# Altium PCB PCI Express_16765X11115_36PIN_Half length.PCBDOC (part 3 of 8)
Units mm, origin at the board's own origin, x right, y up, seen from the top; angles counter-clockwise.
Board outline 178 x 110.97 mm, 10 copper layers (Top Layer, Int1 (GND), Int2 (Sign), Int3 (Sign), Int4 (PWR), Int5 (GND), Int6 (Sign), Int7 (Sign), Int8 (GND), Bottom Layer), stack 1.429 mm thick; 528 components, 525 nets, 2272 pads, 1491 vias.
Unrouted connection lines stored in the file: 373.
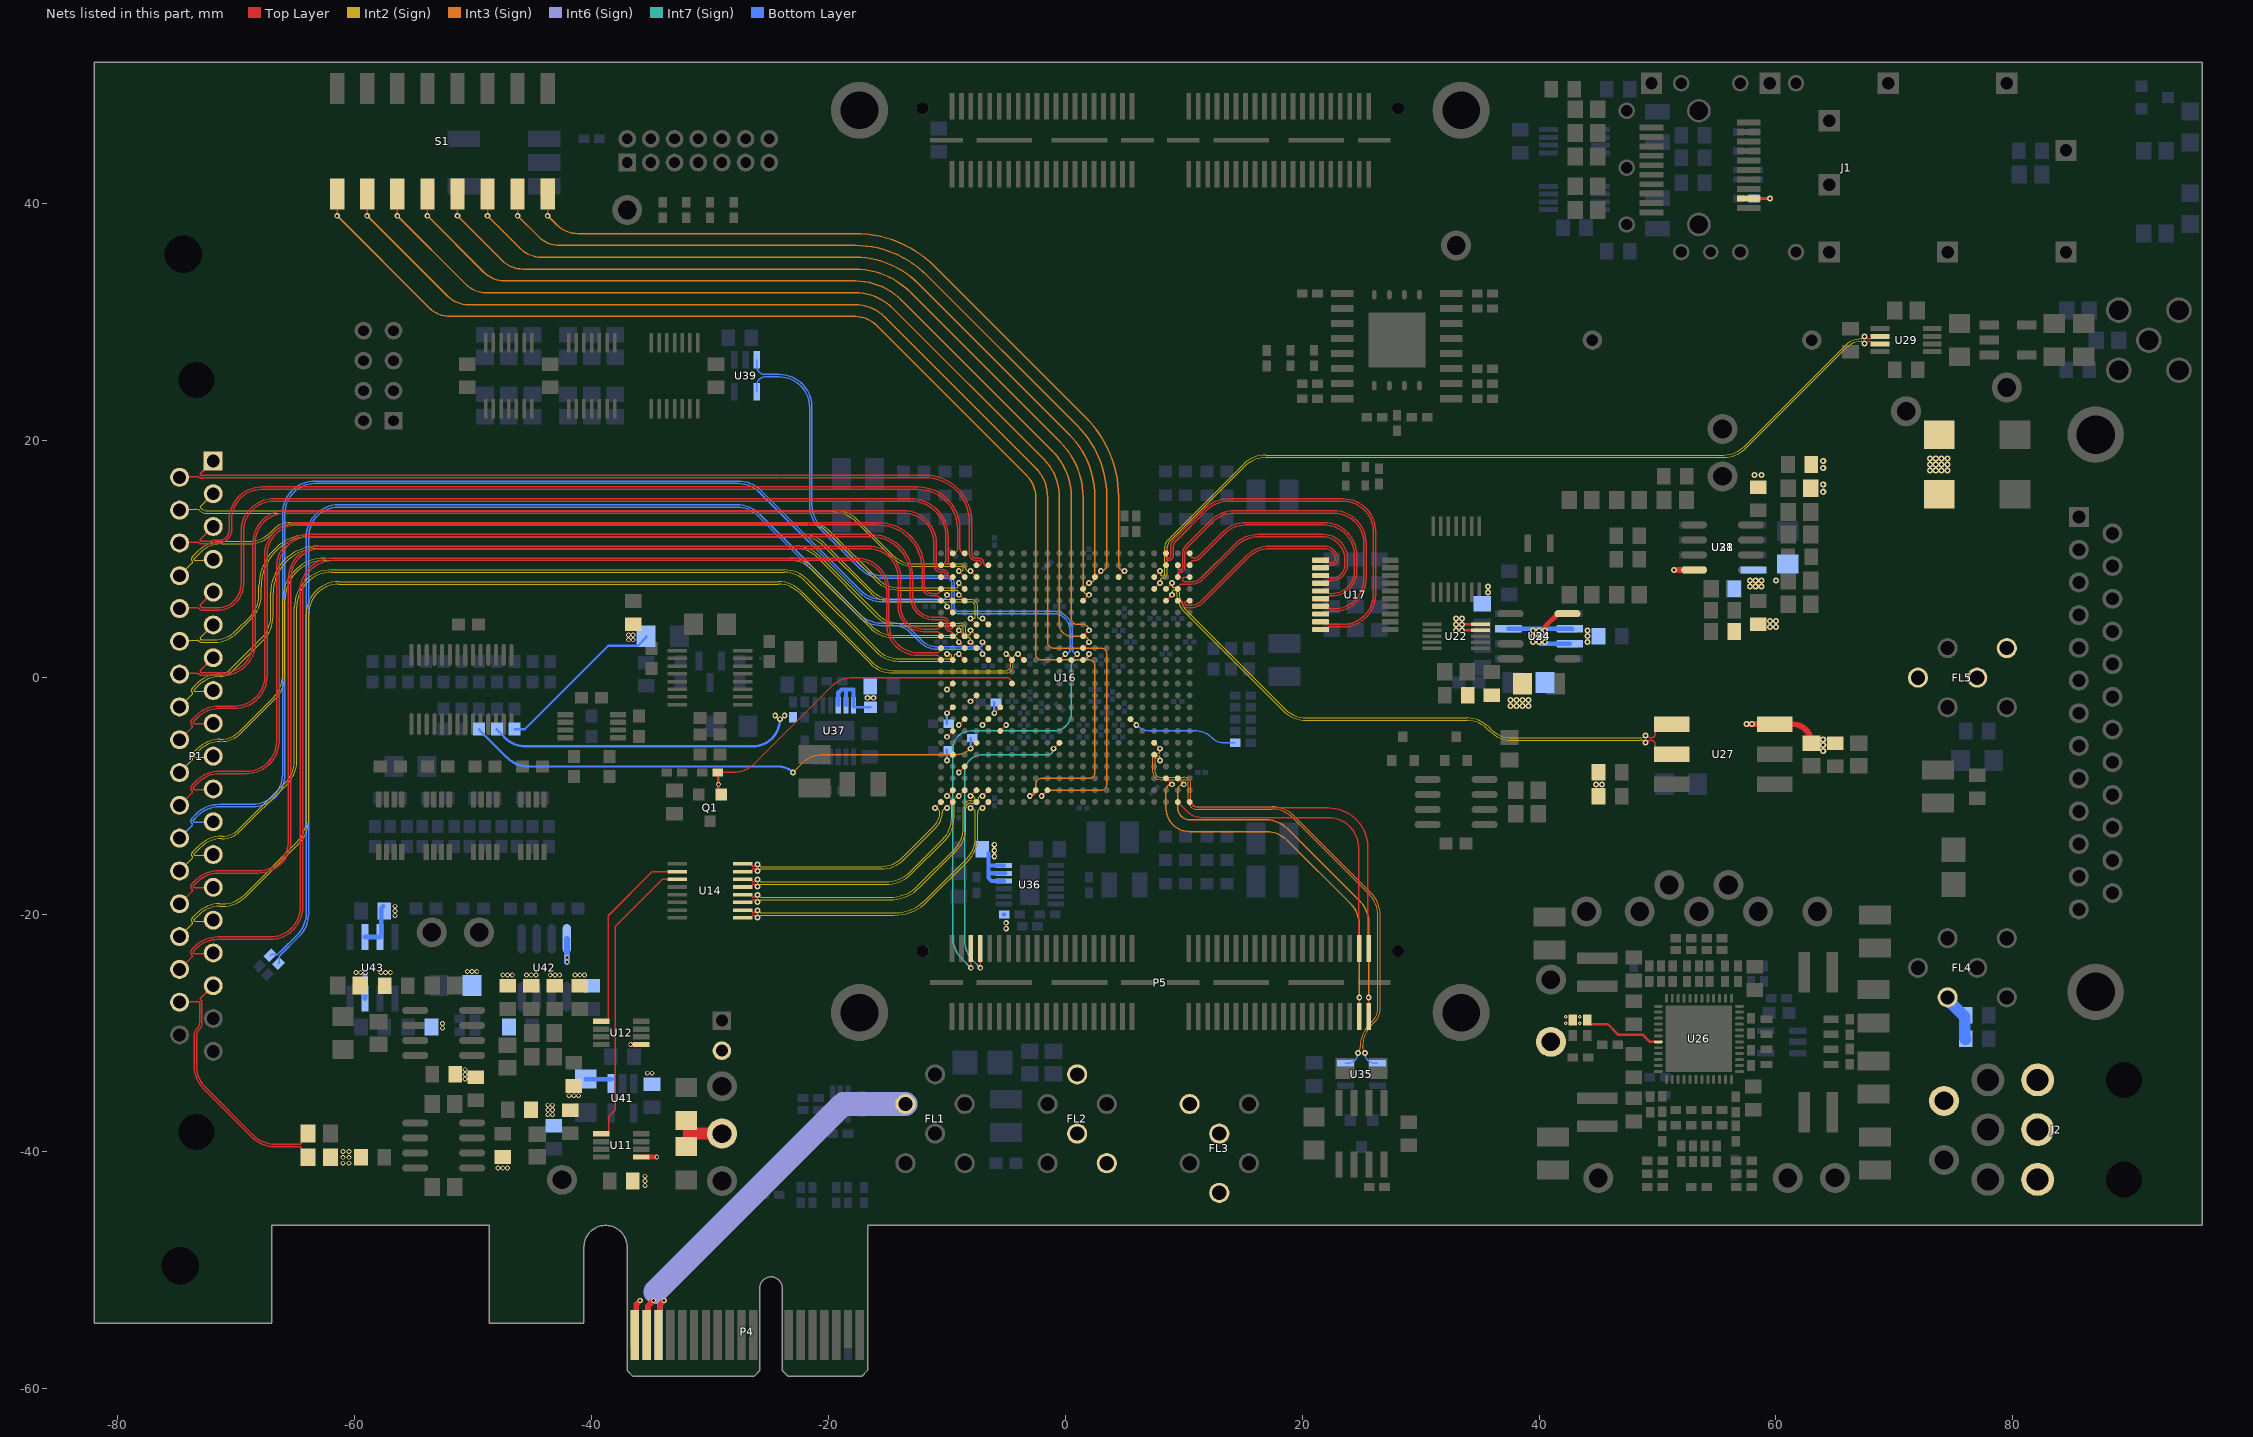
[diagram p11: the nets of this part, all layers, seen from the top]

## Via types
v1: diameter 0.483, hole 0.254, Top Layer to Bottom Layer, tented both sides, 740 vias
v2: diameter 0.508, hole 0.254, Top Layer to Bottom Layer, tented both sides, 302 vias
v3: diameter 0.406, hole 0.254, Top Layer to Bottom Layer, tented both sides, 267 vias
v4: diameter 0.305, hole 0.152, Top Layer to Bottom Layer, tented both sides, 95 vias
v5: diameter 0.5, hole 0.254, Top Layer to Bottom Layer, tented both sides, 50 vias
v6: diameter 0.45, hole 0.254, Top Layer to Bottom Layer, tented both sides, 23 vias
v7: diameter 0.6, hole 0.254, Top Layer to Bottom Layer, tented both sides, 14 vias

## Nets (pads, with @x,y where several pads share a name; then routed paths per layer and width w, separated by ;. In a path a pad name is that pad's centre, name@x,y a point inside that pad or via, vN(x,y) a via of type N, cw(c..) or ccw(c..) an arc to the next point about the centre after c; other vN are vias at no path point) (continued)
AGND: C30.1 C33.1 C34.2 C38.1 C39.1 C54.1 C62.1 C63.1 C65.1 C66.2 C71.2 C72.2 C81.2 C82.1 C88.1 C90.2 FL5.4 FL5.5 FL5.6 R91.2 R92.2 R128.2 U22.4 U22.5 U24.4 U27.3 U28.4 U31.4 U34.3 U34.6 U34.7 | length 22.5
  Top Layer w0.203: U22.4@35.05,4 v2(33.5,4) v2(33.5,4.5) U22.5@35.05,4.5 ; C66.2@64.95,-5.55 ccw(c64.95,-5.5) C66.2@65,-5.5
  Top Layer w0.406: v2(40.5,4) 40.52,4.02 40.52,4.325 41.6,5.405 U24.4@42.4,5.405 U24.4@42.403,5.403
  Top Layer w0.5: v2(51.4,9.1) 53.095,9.1 U28.4@53.1,9.095 ; v2(57.537,-3.92) v2(58,-3.92) U27.3@59.9,-3.92 61.37,-3.92 cw(c61.37,-5.55) R92.2@63,-5.55
  Bottom Layer w0.406: U34.3@37.4,4.135 U34.6@42.6,4.135 42.765,4.135 U34.6@42.8,4.1 ; v2(40,3) 40.135,2.865 U34.7@42.6,2.865
  other v2: 44.8,-9 45.3,-9 64,-6.2 64,-5.7 64,-5.2 37.6,-2.4 38.1,-2.4 38.6,-2.4 39.1,-2.4 37.6,-1.9 38.1,-1.9 38.6,-1.9 39.1,-1.9 39.5,3 40.5,3 44.1,3 39.5,3.5 40,3.5 40.5,3.5 44.1,3.5 33,4 39.5,4 40,4 44.1,4 59.5,4.3 60,4.3 33,4.502 59.5,4.8 60,4.8 33,5 33.5,5 35.7,7.2 35.7,7.7 57.8,7.7 58.3,7.7 58.8,7.7 57.8,8.2 58.3,8.2 58.8,8.2 60,8.2 64,15.7 64,16.3 58.2,17.1 58.8,17.1 73,17.5 73.5,17.5 74,17.5 74.5,17.5 64,17.7 73,18 73.5,18 74,18 74.5,18 64,18.3 73,18.5 73.5,18.5 74,18.5 74.5,18.5
AVCC: C161.2 C165.2 C166.2 R140.2 R181.1 U16.D6 U16.D10 U16.E8 U16.F7 U16.F9 U36.10 U36.11 U36.12 | length 55.2
  Top Layer w0.127: v1(-8,-6) U16.D6@-7.5,-5.5 ; v1(-8,-2) U16.D10@-7.5,-1.5 ; v1(-7,-4) U16.E8@-6.5,-3.5 ; v1(-6,-3) U16.F9@-5.5,-2.5 ; U16.F7@-5.5,-4.5 v1(-5,-4)
  Int3 (Sign) w0.127: v1(-23,-8) -22.244,-7.244 cw(c-20.448,-9.04) -20.448,-6.5 -9.207,-6.5 ccw(c-9.207,-4.793) v1(-8,-6)
  Bottom Layer w0.127: C161.2@-6.1,-2 C161.2@-6,-2.1
  Bottom Layer w0.203: R181.1@-49.5,-4.35 -49.5,-4.4 -47.144,-6.756 ccw(c-45.348,-4.96) -45.348,-7.5 -24.207,-7.5 cw(c-24.207,-9.207) v1(-23,-8) ; v1(-8,-6) C166.2@-8,-5.1 ; v1(-6,-3) C161.2@-6,-2.1
  Bottom Layer w0.35: C165.2@-6.5,-14.8 -6.5,-15.9 ; -6.351,-16.519 U36.11@-5.061,-16.519 ; R140.2@-5.225,-20 R140.2@-5.15,-20 ; U36.12@-5.209,-15.9 U36.12@-5.184,-15.875 -6.475,-15.875 -6.5,-15.9 ; U36.10@-5.184,-17.175 -6.225,-17.175 -6.5,-16.9 -6.5,-15.9
  other v1: -5,-21.2 -5,-20.7 -6,-15.1 -6,-14.6 -6,-14.1
AVCC1V8: C18.1 C37.2 FR5.1 R58.2 R170.1 TP9.1 U26.7 | length 21.2
  Top Layer w0.203: C37.2@44.062,-28.912 44.062,-29.012 44.311,-29.261 45.821,-29.261 46.719,-30.159 48.793,-30.159 49.383,-30.75 U26.7@50.075,-30.75
  Bottom Layer w0.203: R170.1@-46.5,-4.35 -45.65,-4.35 -38.6,2.7 -36.217,2.7 -36.216,2.702 -36.098,2.702 -35.4,3.4 FR5.1@-35.4,3.5
  other v3: -36.9,3.2 -36.5,3.2 -36.9,3.6 -36.5,3.6
  other v4: 42.25,-29.187 43.437,-29.187 42.25,-28.625 43.437,-28.625
AVTT: C173.2 C174.2 C181.2 R144.2 R152.2 R175.1 U16.B5 U16.B7 U16.B9 U16.B11 U16.C4 U16.C8 U37.10 U37.11 U37.12 | length 38.3
  Top Layer w0.127: v1(-10,-7) U16.B5@-9.5,-6.5 ; v1(-10,-5) U16.B7@-9.5,-4.5 ; v1(-10,-3) U16.B9@-9.5,-2.5 ; v1(-10,-1) U16.B11@-9.5,-0.5 ; v1(-9,-8) U16.C4@-8.5,-7.5 ; v1(-9,-4) U16.C8@-8.5,-3.5
  Bottom Layer w0.203: R175.1@-48,-4.35 -48,-4.4 -47.342,-5.058 ccw(c-45.546,-3.262) -45.546,-5.802 -28.7,-5.802 ; -28.7,-5.8 -26.4,-5.8 ccw(c-26.4,-3.5) v1(-24.1,-3.5) ; U37.12@-17.9,-2.5 R144.2@-16.45,-2.5 ; v1(-10,-7) C173.2@-10,-6.1 ; C174.2@-10,-3.9 v1(-10,-3)
  Bottom Layer w0.35: U37.10@-19.175,-2.316 -19.175,-1.275 -18.9,-1 -17.875,-1 U37.12@-17.875,-2.316 ; U37.11@-18.525,-2.316 -18.525,-1.025
  other v1: -24.5,-3.2 -23.7,-3.2 -16.7,-1.7 -16.2,-1.7
BACKPLANE.CLK0_N: P1.21 U16.C20 | length 69.3
  Top Layer w0.127: v1(-9,9) U16.C20@-8.5,8.5
  Int2 (Sign) w0.076: P1.21@-74.795,14.15 cw(c-74.615,13.97) -74.615,14.225 -73.434,14.225 cw(c-73.434,13.665) -73.038,14.061 ccw(c-72.642,14.457) -72.642,13.897 -19.449,13.897 cw(c-19.449,11.357) -17.653,13.153 -14.703,10.203 ccw(c-12.764,12.142) -12.764,9.4 -8.802,9.4 cw(c-8.802,9.2) -8.602,9.2 cw(c-8.802,9.2) -8.802,9 v1(-9,9)
BACKPLANE.CLK0_P: P1.2 U16.D20 | length 69.4
  Top Layer w0.127: v1(-8,9) U16.D20@-7.5,8.5
  Int2 (Sign) w0.076: P1.2@-71.955,15.535 -73.036,14.454 ccw(c-72.982,14.4) -73.059,14.4 ccw(c-72.982,14.4) -73.036,14.346 ccw(c-72.442,14.94) -72.442,14.1 -19.448,14.1 cw(c-19.448,11.359) -17.51,13.297 -14.56,10.347 ccw(c-12.764,12.143) -12.764,9.603 -8.802,9.603 cw(c-8.802,9.2) -8.398,9.2 ccw(c-8.198,9.2) -8.198,9 v1(-8,9)
BACKPLANE.CLK1_N: P1.30 U16.B16 | length 90.3
  Top Layer w0.127: P1.30@-74.795,-10.78 -73.75,-9.735 ccw(c-73.84,-9.645) -73.713,-9.645 ccw(c-73.84,-9.645) -73.75,-9.555 ; -73.751,-9.554 cw(c-73.519,-9.323) -73.846,-9.323 -73.846,-9.32 cw(c-73.52,-9.32) -73.751,-9.089 -73.361,-8.7 cw(c-71.423,-10.637) -71.423,-7.897 -69.143,-7.897 ccw(c-69.143,-5.357) -66.603,-5.357 -66.603,9.36 cw(c-63.86,9.36) -63.86,12.103 -16.453,12.103 cw(c-16.453,8.547) -12.897,8.547 -12.897,6.793 ccw(c-11.098,6.9) -11.098,5.098 -10.336,5.098 cw(c-10.336,4.662) -9.9,4.662 -9.9,4.281 ccw(c-9.721,4.281) -9.721,4.102 ccw(c-9.721,4.323) -9.5,4.323 U16.B16@-9.5,4.5
BACKPLANE.CLK1_P: P1.11 U16.B15 | length 89.8
  Top Layer w0.127: P1.11@-71.955,-9.395 cw(c-72.084,-9.266) -72.084,-9.449 -73.516,-9.449 cw(c-73.516,-9.322) -73.606,-9.411 cw(c-73.516,-9.322) -73.643,-9.322 cw(c-73.516,-9.322) -73.606,-9.232 -73.218,-8.844 cw(c-71.422,-10.64) -71.422,-8.1 -69.143,-8.1 ccw(c-69.143,-5.357) -66.4,-5.357 -66.4,9.36 cw(c-63.86,9.36) -63.86,11.9 -16.453,11.9 cw(c-16.453,8.547) -13.1,8.547 -13.1,6.787 ccw(c-11.098,6.9) -11.098,4.895 -10.336,4.895 cw(c-10.336,4.662) -10.103,4.662 -10.103,4.281 ccw(c-9.721,4.281) -9.721,3.898 cw(c-9.721,3.677) -9.5,3.677 U16.B15@-9.5,3.5
BACKPLANE.CLK2_N: P1.29 U16.C15 | length 81.6
  Top Layer w0.127: v1(-9,4) U16.C15@-8.5,3.5
  Int2 (Sign) w0.076: P1.29@-74.795,-8.01 -73.714,-6.929 ccw(c-73.768,-6.875) -73.691,-6.875 ccw(c-73.768,-6.875) -73.714,-6.821 ; -73.796,-6.624 ccw(c-73.518,-6.624) -73.714,-6.82 ; -73.796,-6.623 cw(c-73.517,-6.623) -73.714,-6.426 -73.287,-6 cw(c-71.349,-7.937) -71.349,-5.197 ccw(c-71.349,-2.897) -69.723,-4.523 -66.847,-1.647 ccw(c-68.643,0.149) -66.103,0.149 -66.103,6.547 cw(c-62.547,6.547) -62.547,10.103 -23.239,10.103 cw(c-23.239,7.362) -21.3,9.3 -16.346,4.346 ccw(c-14.55,6.142) -14.55,3.602 -9.398,3.602 ccw(c-9.398,4) v1(-9,4)
BACKPLANE.CLK2_P: P1.10 U16.C14 | length 81.2
  Top Layer w0.127: v1(-9,3) U16.C14@-8.5,2.5
  Int2 (Sign) w0.076: P1.10@-71.955,-6.625 cw(c-72.135,-6.445) -72.135,-6.7 -73.516,-6.7 cw(c-73.516,-6.623) -73.57,-6.677 cw(c-73.516,-6.623) -73.592,-6.623 cw(c-73.516,-6.623) -73.57,-6.57 -73.144,-6.144 cw(c-71.348,-7.94) -71.348,-5.4 ccw(c-71.348,-2.899) -69.58,-4.668 -66.703,-1.79 ccw(c-68.641,0.148) -65.9,0.148 -65.9,6.547 cw(c-62.547,6.547) -62.547,9.9 -23.239,9.9 cw(c-23.239,7.36) -21.443,9.156 -16.489,4.201 ccw(c-14.55,6.14) -14.554,3.398 ccw(c-14.55,6.14) -14.55,3.398 -9.398,3.398 cw(c-9.398,3) v1(-9,3)
BACKPLANE.CLK3_N: P1.28 U16.A19 | length 83.3
  Top Layer w0.127: P1.28@-74.795,-5.24 -73.75,-4.195 ccw(c-73.84,-4.105) -73.713,-4.105 ccw(c-73.84,-4.105) -73.75,-4.015 ; -73.751,-4.014 cw(c-73.519,-3.783) -73.846,-3.783 -73.846,-3.78 cw(c-73.52,-3.78) -73.751,-3.549 -73.401,-3.2 cw(c-71.463,-5.137) -71.463,-2.397 -70.143,-2.397 ccw(c-70.143,0.143) -67.603,0.143 -67.603,10.36 cw(c-64.86,10.36) -64.86,13.103 -15.859,13.103 cw(c-15.859,9.141) -11.897,9.141 -11.897,7.735 ccw(c-11.2,7.802) -11.2,7.102 -10.898,7.102 ccw(c-10.898,7.5) U16.A19@-10.5,7.5
BACKPLANE.CLK3_P: P1.9 U16.A18 | length 82.8
  Top Layer w0.127: P1.9@-71.955,-3.855 cw(c-72.084,-3.726) -72.084,-3.909 -73.516,-3.909 cw(c-73.516,-3.782) -73.606,-3.871 cw(c-73.516,-3.782) -73.643,-3.782 cw(c-73.516,-3.782) -73.606,-3.692 -73.258,-3.344 cw(c-71.462,-5.14) -71.462,-2.6 -70.143,-2.6 ccw(c-70.143,0.143) -67.4,0.143 -67.4,10.36 cw(c-64.86,10.36) -64.86,12.9 -15.859,12.9 cw(c-15.859,9.141) -12.1,9.141 -12.1,7.726 ccw(c-11.2,7.802) -11.2,6.898 -10.898,6.898 cw(c-10.898,6.5) U16.A18@-10.5,6.5
BACKPLANE.CLK4_N: P1.27 U16.D15 | length 79.1
  Top Layer w0.127: v1(-8,4) U16.D15@-7.5,3.5
  Int2 (Sign) w0.076: P1.27@-74.795,-2.47 -73.714,-1.389 ccw(c-73.768,-1.335) -73.691,-1.335 ccw(c-73.768,-1.335) -73.714,-1.281 ; -73.796,-1.084 ccw(c-73.518,-1.084) -73.714,-1.28 ; -73.796,-1.083 cw(c-73.517,-1.083) -73.714,-0.886 -73.327,-0.5 cw(c-71.389,-2.437) -71.389,0.303 ccw(c-71.389,1.493) -70.548,0.652 -67.847,3.353 ccw(c-69.643,5.149) -67.103,5.149 -67.103,7.141 cw(c-63.141,7.141) -63.141,11.103 -22.739,11.103 cw(c-22.739,8.362) -20.8,10.3 -15.847,5.347 ccw(c-14.051,7.143) -14.051,4.603 -8.903,4.603 cw(c-8.903,4.1) -8.4,4.1 -8.4,3.802 ccw(c-8.2,3.802) -8.2,3.602 ccw(c-8.2,3.802) -8,3.802 v1(-8,4)
BACKPLANE.CLK4_P: P1.8 U16.D14 | length 78.6
  Top Layer w0.127: v1(-8,3) U16.D14@-7.5,2.5
  Int2 (Sign) w0.076: P1.8@-71.955,-1.085 cw(c-72.135,-0.905) -72.135,-1.16 -73.516,-1.16 cw(c-73.516,-1.083) -73.57,-1.137 cw(c-73.516,-1.083) -73.592,-1.083 cw(c-73.516,-1.083) -73.57,-1.03 -73.184,-0.644 cw(c-71.388,-2.44) -71.388,0.1 ; -71.387,0.1 ccw(c-71.387,1.487) -70.406,0.506 -67.701,3.212 ccw(c-69.634,5.145) -66.9,5.145 -66.9,7.141 cw(c-63.141,7.141) -63.141,10.9 -34.4,10.9 -25.4,10.9 -22.739,10.9 cw(c-22.739,8.36) -20.943,10.156 -15.99,5.203 ccw(c-14.052,7.142) -14.055,4.4 ccw(c-14.052,7.142) -14.052,4.4 -8.903,4.4 cw(c-8.903,4.1) -8.603,4.1 -8.603,3.802 ccw(c-8.2,3.802) -8.2,3.398 cw(c-8.2,3.198) -8,3.198 v1(-8,3)
BACKPLANE.CLK5_N: P1.26 U16.A20 | length 80.5
  Top Layer w0.127: P1.26@-74.795,0.3 cw(c-74.666,0.171) -74.666,0.354 -73.292,0.354 cw(c-73.292,0.086) -73.103,0.275 ccw(c-72.913,0.465) -72.913,0.197 -71.143,0.197 ccw(c-71.143,2.94) -68.4,2.94 -68.4,11.36 cw(c-65.86,11.36) -65.86,13.9 -13.643,13.9 cw(c-13.643,11.36) -11.103,11.36 -11.103,9.526 ccw(c-10.473,9.526) -10.473,8.895 -10.32,8.895 cw(c-10.32,8.677) -10.102,8.677 cw(c-10.279,8.677) -10.279,8.5 U16.A20@-10.5,8.5
BACKPLANE.CLK5_P: P1.7 U16.B20 | length 80.6
  Top Layer w0.127: P1.7@-71.955,1.685 -73,0.64 ccw(c-72.91,0.55) -73.037,0.55 ccw(c-72.91,0.55) -73,0.46 ccw(c-72.855,0.605) -72.855,0.4 -71.143,0.4 ccw(c-71.143,2.94) -68.603,2.94 -68.603,11.36 cw(c-65.86,11.36) -65.86,14.103 -13.643,14.103 cw(c-13.643,11.36) -10.9,11.36 -10.9,9.526 ccw(c-10.473,9.526) -10.473,9.099 -10.32,9.099 cw(c-10.32,8.677) -9.898,8.677 ccw(c-9.721,8.677) -9.721,8.5 U16.B20@-9.5,8.5
BACKPLANE.CLK6_N: P1.25 U16.D16 | length 76.8
  Top Layer w0.127: v1(-8,5) U16.D16@-7.5,4.5
  Int2 (Sign) w0.076: P1.25@-74.795,3.07 cw(c-74.615,2.89) -74.615,3.145 -73.307,3.145 cw(c-73.307,2.892) -73.128,3.071 ccw(c-72.95,3.249) -72.95,2.997 -71.851,2.997 ccw(c-71.851,5.737) -69.913,3.8 -68.703,5.01 ccw(c-70.641,6.948) -67.9,6.948 -67.9,7.734 cw(c-63.734,7.734) -63.734,11.9 -22.239,11.9 cw(c-22.239,9.36) -20.443,11.156 -16.49,7.203 ccw(c-14.552,9.142) -14.555,6.4 ccw(c-14.552,9.142) -14.552,6.4 -8,6.4 cw(c-8,6.002) -7.602,6.002 -7.602,5.1 cw(c-7.702,5.1) -7.702,5 v1(-8,5)
BACKPLANE.CLK6_P: P1.6 U16.E16 | length 77
  Top Layer w0.127: v1(-7,5) U16.E16@-6.5,4.5
  Int2 (Sign) w0.076: P1.6@-71.955,4.455 -73.036,3.374 ccw(c-72.982,3.32) -73.059,3.32 ccw(c-72.982,3.32) -73.036,3.266 ccw(c-72.877,3.425) -72.877,3.2 -71.852,3.2 ccw(c-71.852,5.74) -70.056,3.944 -68.847,5.153 ccw(c-70.643,6.949) -68.103,6.949 -68.103,7.734 cw(c-63.734,7.734) -63.734,12.103 -22.239,12.103 cw(c-22.239,9.362) -20.3,11.3 -16.347,7.347 ccw(c-14.551,9.143) -14.551,6.603 -8,6.603 cw(c-8,6.002) -7.398,6.002 -7.398,5.1 ccw(c-7.298,5.1) -7.298,5 v1(-7,5)
BACKPLANE.CLK7_N: P1.24 U16.A21 | length 76.3
  Top Layer w0.127: P1.24@-74.795,5.84 cw(c-74.666,5.711) -74.666,5.894 -73.32,5.894 cw(c-73.32,5.558) -73.083,5.795 ccw(c-72.845,6.033) -72.845,5.697 -71.599,5.697 ccw(c-71.599,7.899) -69.397,7.899 -69.397,12.362 cw(c-66.857,12.362) -66.857,14.902 -13.048,14.902 cw(c-13.048,11.955) -10.102,11.955 -10.102,9.898 cw(c-10.5,9.898) U16.A21@-10.5,9.5
BACKPLANE.CLK7_P: P1.5 U16.B21 | length 76.5
  Top Layer w0.127: P1.5@-71.955,7.225 -73,6.18 ccw(c-72.91,6.09) -73.037,6.09 ccw(c-72.91,6.09) -73,6 ccw(c-72.759,6.242) -72.759,5.9 -71.6,5.9 ccw(c-71.6,7.9) -69.6,7.9 -69.6,12.362 cw(c-66.857,12.362) -66.857,15.105 -13.048,15.105 cw(c-13.048,11.955) -9.898,11.955 -9.898,9.898 ccw(c-9.5,9.898) U16.B21@-9.5,9.5
BACKPLANE.CLK8_N: P1.23 U16.C19 | length 70.8
  Top Layer w0.127: v1(-9,8) U16.C19@-8.5,7.5
  Int2 (Sign) w0.076: P1.23@-74.795,8.61 -73.714,9.691 ccw(c-73.768,9.745) -73.691,9.745 ccw(c-73.768,9.745) -73.714,9.799 ; -73.796,9.996 ccw(c-73.518,9.996) -73.714,9.8 ; -73.796,9.997 cw(c-73.517,9.997) -73.714,10.194 -73.207,10.7 cw(c-71.269,8.763) -71.269,11.503 -68.949,11.503 ccw(c-68.949,14.043) -67.153,12.247 -66.899,12.501 cw(c-65.445,11.046) -65.445,13.103 -21.737,13.103 cw(c-21.737,10.366) -19.802,12.302 -15.844,8.344 ccw(c-14.048,10.14) -14.048,7.6 -9.118,7.6 -9.029,7.689 -9.029,7.971 v1(-9,8)
BACKPLANE.CLK8_P: P1.4 U16.C18 | length 70.3
  Top Layer w0.127: v1(-9,7) U16.C18@-8.5,6.5
  Int2 (Sign) w0.076: P1.4@-71.955,9.995 cw(c-72.135,10.175) -72.135,9.92 -73.516,9.92 cw(c-73.516,9.997) -73.57,9.943 cw(c-73.516,9.997) -73.592,9.997 cw(c-73.516,9.997) -73.57,10.05 -73.064,10.556 cw(c-71.268,8.76) -71.268,11.3 -68.948,11.3 ccw(c-68.948,14.041) -67.01,12.103 -66.756,12.356 cw(c-65.444,11.044) -65.444,12.9 -21.739,12.9 cw(c-21.739,10.36) -19.943,12.156 -15.987,8.2 ccw(c-14.049,10.139) -14.049,7.397 -9.116,7.397 -9.03,7.311 -9.03,7.03 v1(-9,7)
BACKPLANE.CLK9_N: P1.22 U16.B22 | length 72.9
  Top Layer w0.127: P1.22@-74.795,11.38 cw(c-74.666,11.251) -74.666,11.434 -73.276,11.434 cw(c-73.276,11.205) -73.114,11.367 ccw(c-72.953,11.528) -72.953,11.3 -72.145,11.3 ccw(c-72.145,11.588) -71.941,11.384 ; -71.941,11.385 cw(c-71.904,11.348) -71.904,11.4 -71.497,11.4 ccw(c-71.497,12.5) -70.397,12.5 -70.397,13.362 cw(c-67.857,13.362) -67.857,15.902 -24.103,15.902 ; -24.063,15.902 -12.454,15.902 cw(c-12.454,12.549) -9.102,12.549 -9.102,10.898 cw(c-9.5,10.898) U16.B22@-9.5,10.5
BACKPLANE.CLK9_P: P1.3 U16.C22 | length 73
  Top Layer w0.127: -72.084,11.528 cw(c-72.146,11.59) -72.146,11.503 -72.91,11.503 cw(c-72.91,11.63) -73,11.54 cw(c-72.91,11.63) -73.037,11.63 cw(c-72.91,11.63) -73,11.72 P1.3@-71.955,12.765 ; -72.084,11.529 cw(c-71.905,11.35) -71.905,11.603 -71.497,11.603 ccw(c-71.497,12.5) -70.6,12.5 -70.6,13.362 cw(c-67.857,13.362) -67.857,16.105 -24.019,16.105 ; -23.979,16.105 -12.454,16.105 cw(c-12.454,12.549) -8.898,12.549 -8.898,10.898 ccw(c-8.5,10.898) U16.C22@-8.5,10.5
BACKPLANE.CS_N: P1.32 U16.B13 | length 88.7
  Top Layer w0.127: v1(-10,2) U16.B13@-9.5,1.5
  Int2 (Sign) w0.076: P1.32@-74.795,-16.32 -73.714,-15.239 ccw(c-73.768,-15.185) -73.691,-15.185 ccw(c-73.768,-15.185) -73.714,-15.131 ; -73.714,-15.13 cw(c-73.518,-14.934) -73.796,-14.934 cw(c-73.517,-14.933) -73.714,-14.736 -73.177,-14.2 cw(c-71.239,-16.137) -71.239,-13.397 ccw(c-71.239,-11.362) -69.801,-12.801 -65.847,-8.847 ccw(c-67.643,-7.051) -65.103,-7.051 -65.103,5.954 cw(c-61.954,5.954) -61.954,9.103 -23.739,9.103 cw(c-23.739,6.362) -21.8,8.3 -15.844,2.344 ccw(c-14.048,4.14) -14.048,1.6 -9.802,1.6 ccw(c-9.802,1.8) -9.602,1.8 ccw(c-9.802,1.8) -9.802,2 v1(-10,2)
BACKPLANE.CS_P: P1.13 U16.C13 | length 88.5
  Top Layer w0.127: v1(-9,2) U16.C13@-8.5,1.5
  Int2 (Sign) w0.076: P1.13@-71.955,-14.935 cw(c-72.135,-14.755) -72.135,-15.01 -73.516,-15.01 cw(c-73.516,-14.933) -73.57,-14.987 cw(c-73.516,-14.933) -73.592,-14.933 cw(c-73.516,-14.933) -73.57,-14.88 -73.034,-14.344 cw(c-71.238,-16.14) -71.238,-13.6 ccw(c-71.238,-11.365) -69.658,-12.945 -65.703,-8.99 ccw(c-67.641,-7.052) -64.9,-7.052 -64.9,5.954 cw(c-61.954,5.954) -61.954,8.9 -23.739,8.9 cw(c-23.739,6.36) -21.943,8.156 -15.987,2.2 ccw(c-14.048,4.139) -14.048,1.397 -9.802,1.397 ccw(c-9.802,1.8) -9.398,1.8 cw(c-9.198,1.8) -9.198,2 v1(-9,2)
BACKPLANE.DIN_N: P1.35 U16.A14 | length 101.5
  Top Layer w0.127: P1.35@-74.795,-24.63 -73.75,-23.585 ccw(c-73.84,-23.495) -73.713,-23.495 ccw(c-73.84,-23.495) -73.75,-23.405 cw(c-73.519,-23.173) -73.846,-23.173 -73.846,-23.17 cw(c-73.52,-23.17) -73.751,-22.939 -73.511,-22.7 cw(c-71.573,-24.637) -71.573,-21.897 -67.143,-21.897 ccw(c-67.143,-19.357) -64.603,-19.357 -64.603,7.36 cw(c-61.86,7.36) -61.86,10.103 -17.64,10.103 cw(c-17.64,7.36) -14.897,7.36 -14.897,4.598 ccw(c-12.4,4.598) -12.4,2.102 -10.898,2.102 ccw(c-10.898,2.5) U16.A14@-10.5,2.5
BACKPLANE.DIN_P: P1.16 U16.A13 | length 101
  Top Layer w0.127: P1.16@-71.955,-23.245 cw(c-72.084,-23.116) -72.084,-23.299 -73.516,-23.299 cw(c-73.516,-23.172) -73.606,-23.261 cw(c-73.516,-23.172) -73.643,-23.172 cw(c-73.516,-23.172) -73.606,-23.082 -73.368,-22.844 cw(c-71.572,-24.64) -71.572,-22.1 -67.143,-22.1 ccw(c-67.143,-19.357) -64.4,-19.357 -64.4,7.36 cw(c-61.86,7.36) -61.86,9.9 -17.64,9.9 cw(c-17.64,7.36) -15.1,7.36 -15.1,4.514 ccw(c-12.484,4.514) -12.484,1.898 -10.898,1.898 cw(c-10.898,1.5) U16.A13@-10.5,1.5
BACKPLANE.DOUT_N: P1.34 U16.G13 | length 98.9
  Top Layer w0.127: v1(-5,2) U16.G13@-4.5,1.5
  Int2 (Sign) w0.076: P1.34@-74.795,-21.86 -73.714,-20.779 ccw(c-73.768,-20.725) -73.691,-20.725 ccw(c-73.768,-20.725) -73.714,-20.671 ; -73.796,-20.474 ccw(c-73.518,-20.474) -73.714,-20.67 ; -73.796,-20.473 cw(c-73.517,-20.473) -73.714,-20.276 -73.337,-19.9 cw(c-71.399,-21.837) -71.399,-19.097 -71.149,-19.097 ccw(c-71.149,-16.557) -69.353,-18.353 -64.847,-13.847 ccw(c-66.643,-12.051) -64.103,-12.051 -64.103,5.36 cw(c-61.36,5.36) -61.36,8.103 -24.238,8.103 cw(c-24.238,5.364) -22.301,7.301 -16.344,1.344 ccw(c-14.548,3.14) -14.548,0.6 -5.002,0.6 ccw(c-5.002,1) -4.602,1 -4.602,1.602 ccw(c-5,1.602) v1(-5,2)
BACKPLANE.DOUT_P: P1.15 U16.H13 | length 98.7
  Top Layer w0.127: v1(-4,2) U16.H13@-3.5,1.5
  Int2 (Sign) w0.076: P1.15@-71.955,-20.475 cw(c-72.135,-20.295) -72.135,-20.55 -73.516,-20.55 cw(c-73.516,-20.473) -73.57,-20.527 cw(c-73.516,-20.473) -73.592,-20.473 cw(c-73.516,-20.473) -73.57,-20.42 -73.194,-20.044 cw(c-71.398,-21.84) -71.398,-19.3 -71.148,-19.3 ccw(c-71.148,-16.559) -69.21,-18.497 -64.703,-13.99 ccw(c-66.641,-12.052) -63.9,-12.052 -63.9,5.36 cw(c-61.36,5.36) -61.36,7.9 -24.239,7.9 cw(c-24.239,5.36) -22.443,7.156 -16.487,1.2 ccw(c-14.549,3.139) -14.549,0.397 -5.002,0.397 ccw(c-5.002,1) -4.398,1 -4.398,1.602 cw(c-4,1.602) v1(-4,2)
BACKPLANE.SCLK_N: P1.33 U16.A16 | length 96.2
  Top Layer w0.127: P1.33@-74.795,-19.09 -73.75,-18.045 ccw(c-73.84,-17.955) -73.713,-17.955 ccw(c-73.84,-17.955) -73.75,-17.865 ; -73.751,-17.864 cw(c-73.519,-17.633) -73.846,-17.633 -73.846,-17.63 cw(c-73.52,-17.63) -73.751,-17.399 -73.451,-17.1 cw(c-71.513,-19.037) -71.513,-16.297 -68.143,-16.297 ccw(c-68.143,-13.757) -65.603,-13.757 -65.603,8.36 cw(c-62.86,8.36) -62.86,11.103 -16.643,11.103 cw(c-16.643,8.36) -13.9,8.36 -13.9,6 ccw(c-12.002,6) -12.002,4.102 -10.898,4.102 ccw(c-10.898,4.5) U16.A16@-10.5,4.5
BACKPLANE.SCLK_P: P1.14 U16.A15 | length 95.7
  Top Layer w0.127: P1.14@-71.955,-17.705 cw(c-72.084,-17.576) -72.084,-17.759 -73.516,-17.759 cw(c-73.516,-17.632) -73.606,-17.721 cw(c-73.516,-17.632) -73.643,-17.632 cw(c-73.516,-17.632) -73.606,-17.542 -73.308,-17.244 cw(c-71.512,-19.04) -71.512,-16.5 -68.143,-16.5 ccw(c-68.143,-13.757) -65.4,-13.757 -65.4,8.36 cw(c-62.86,8.36) -62.86,10.9 -16.643,10.9 cw(c-16.643,8.36) -14.103,8.36 -14.103,6 ccw(c-12.002,6) -12.002,3.898 -10.898,3.898 cw(c-10.898,3.5) U16.A15@-10.5,3.5
BACKPLANE.X1_N: R202.1 U16.E14 | length 101
  Top Layer w0.127: v1(-7,3) U16.E14@-6.5,2.5
  Bottom Layer w0.127: R202.1@-67.14,-23.44 cw(c-66.97,-23.611) -66.97,-23.37 -66.681,-23.37 cw(c-66.681,-23.409) -66.653,-23.381 ccw(c-66.625,-23.353) -66.625,-23.393 ccw(c-66.625,-23.178) -66.474,-23.33 -66.289,-23.145 -64.847,-21.703 ccw(c-66.643,-19.907) -64.103,-19.907 -64.103,11.858 cw(c-61.36,11.858) -61.36,14.602 -27.737,14.602 cw(c-27.737,11.861) -25.799,13.799 -17.347,5.347 ccw(c-15.551,7.143) -15.551,4.603 -14.454,4.603 cw(c-14.454,2.55) -13.002,4.002 -12.196,3.196 ccw(c-10.761,4.631) -10.761,2.602 -7.196,2.602 ccw(c-7.196,2.797) -7,2.797 v1(-7,3)
BACKPLANE.X1_P: R201.1 U16.E13 | length 100.9
  Top Layer w0.127: v1(-7,2) U16.E13@-6.5,1.5
  Bottom Layer w0.127: R201.1@-66.44,-24.14 ccw(c-66.611,-23.97) -66.37,-23.97 -66.37,-23.681 ccw(c-66.409,-23.681) -66.381,-23.653 cw(c-66.353,-23.625) -66.393,-23.625 cw(c-66.178,-23.625) -66.33,-23.473 -64.703,-21.847 ccw(c-66.642,-19.908) -63.9,-19.908 -63.9,11.858 cw(c-61.36,11.858) -61.36,14.398 -27.738,14.398 cw(c-27.738,11.858) -25.942,13.655 -17.49,5.203 ccw(c-15.552,7.142) -17.488,5.2 ccw(c-15.552,7.142) -15.552,4.4 -14.456,4.4 cw(c-14.456,2.544) -13.144,3.856 -12.339,3.052 ccw(c-10.762,4.628) -10.766,2.398 ccw(c-10.762,4.628) -10.762,2.398 -7.196,2.398 cw(c-7.196,2.203) -7,2.203 v1(-7,2)
BACKPLANE.X3_N: P1.31 U16.B18 | length 96.2
  Top Layer w0.127: v1(-10,7) U16.B18@-9.5,6.5
  Bottom Layer w0.127: P1.31@-74.795,-13.55 -73.75,-12.505 ccw(c-73.84,-12.415) -73.713,-12.415 ccw(c-73.84,-12.415) -73.75,-12.325 ; -73.751,-12.324 cw(c-73.519,-12.093) -73.846,-12.093 -73.846,-12.09 cw(c-73.52,-12.09) -73.751,-11.859 -73.391,-11.5 cw(c-71.453,-13.437) -71.453,-10.697 -68.643,-10.697 ccw(c-68.643,-8.157) -66.103,-8.157 -66.103,13.86 cw(c-63.36,13.86) -63.36,16.603 -27.639,16.603 cw(c-27.639,13.862) -25.7,15.8 -17.246,7.346 ccw(c-15.45,9.142) -15.45,6.602 -10.398,6.602 ccw(c-10.398,7) v1(-10,7)
BACKPLANE.X3_P: P1.12 U16.B17 | length 95.7
  Top Layer w0.127: v1(-10,6) U16.B17@-9.5,5.5
  Bottom Layer w0.127: P1.12@-71.955,-12.165 cw(c-72.084,-12.036) -72.084,-12.219 -73.516,-12.219 cw(c-73.516,-12.092) -73.606,-12.181 cw(c-73.516,-12.092) -73.643,-12.092 cw(c-73.516,-12.092) -73.606,-12.002 -73.248,-11.644 cw(c-71.452,-13.44) -71.452,-10.9 -68.643,-10.9 ccw(c-68.643,-8.157) -65.9,-8.157 -65.9,13.86 cw(c-63.36,13.86) -63.36,16.4 -27.639,16.4 cw(c-27.639,13.86) -25.843,15.656 -17.389,7.201 ccw(c-15.45,9.14) -15.45,6.398 -10.398,6.398 cw(c-10.398,6) v1(-10,6)
BACKPLANE.X5_N: P1.20 U16.D21 | length 73.4
  Top Layer w0.127: P1.20@-74.795,16.92 cw(c-74.666,16.791) -74.666,16.974 -73.276,16.974 cw(c-73.276,16.745) -73.114,16.907 ccw(c-72.953,17.068) -72.953,16.84 -72.818,16.84 ccw(c-72.818,16.947) -72.742,16.871 cw(c-72.666,16.795) -72.666,16.903 -24.103,16.903 ; -24.019,16.903 -11.86,16.903 cw(c-11.86,13.143) -8.101,13.143 -8.101,10.467 ccw(c-7.527,10.467) -7.527,9.893 -7.329,9.893 cw(c-7.329,9.665) -7.102,9.665 cw(c-7.267,9.665) -7.267,9.5 U16.D21@-7.5,9.5
BACKPLANE.X5_P: P1.1 U16.E21 | length 73.6
  Top Layer w0.127: P1.1@-71.955,18.305 -73,17.26 ccw(c-72.91,17.17) -73.037,17.17 ccw(c-72.91,17.17) -73,17.08 ccw(c-72.91,17.17) -72.91,17.043 -72.902,17.043 ccw(c-72.902,17.15) -72.826,17.074 cw(c-72.751,16.998) -72.751,17.106 -24.019,17.106 ; -23.935,17.106 -11.86,17.106 cw(c-11.86,13.143) -7.897,13.143 -7.897,10.467 ccw(c-7.527,10.467) -7.527,10.096 -7.329,10.096 cw(c-7.329,9.665) -6.898,9.665 ccw(c-6.733,9.665) -6.733,9.5 U16.E21@-6.5,9.5
BGND: C2.1 C3.1 C4.1 C7.2 C8.2 C9.2 C10.2 C11.1 C13.2 C14.2 C15.2 C16.2 C17.2 C20.1 C21.1 C195.1 C198.2 C200.1 C201.2 C203.1 C205.1 C207.1 C209.1 FL2.4 FL2.5 FL2.6 FL3.4 FL3.5 FL3.6 R1.1 R3.1 TP6.1 U11.5 U12.5 U41.1 U42.4 U43.3 U43.6 U43.7 W1.2 | length 17.9
  Top Layer w0.4: U11.5@-35.8,-40.475 v3(-34.5,-40.475)
  Top Layer w0.406: v3(-36.703,-30.975) U12.5@-35.8,-30.975
  Top Layer w0.5: C3.1@-57.6,-26 C3.1@-57.5,-25.9
  Top Layer w1: C20.1@-32,-39.6 -31.8,-39.4 -31.8,-38.5 ; C21.1@-32,-37.4 -31.8,-37.6 -31.8,-38.5 ; TP6.1@-29,-38.5 -31.8,-38.5
  Bottom Layer w0.4: v3@-59.2,-25 -59.135,-25 U43.3@-59.135,-27.1 ; U43.6@-59.135,-21.9 U43.7@-57.9,-21.9 ; U43.7@-57.865,-21.9 -57.765,-21.8 -57.765,-19.465 C209.1@-57.6,-19.3 ; -47.5,-26 -47.4,-26.1 ; C200.1@-40.5,-33.9 U41.1@-38.3,-33.9
  Bottom Layer w0.5: v3(-42.095,-24) U42.4@-42.095,-22.05
  other v3: -35.5,-42.9 -35.5,-42.5 -35.5,-42.1 -47.9,-41.4 -47.5,-41.4 -47.1,-41.4 -61,-41 -60.5,-41 -61,-40.5 -60.5,-40.5 -61,-40 -60.5,-40 -43.7,-36.9 -43.3,-36.9 -43.7,-36.5 -43.3,-36.5 -43.7,-36.1 -43.3,-36.1 -41.9,-35.3 -41.5,-35.3 -41.1,-35.3 -50.7,-33.9 -50.7,-33.5 -35.3,-33.4 -34.9,-33.4 -50.7,-33.1 -52.6,-29.6 -52.6,-29.2 -47.5,-25.1 -47.1,-25.1 -46.7,-25.1 -45.5,-25.1 -45.1,-25.1 -44.7,-25.1 -43.5,-25.1 -43.1,-25.1 -42.7,-25.1 -41.4,-25.1 -41,-25.1 -40.6,-25.1 -59.9,-24.9 -59.5,-24.9 -59.1,-24.9 -57.8,-24.9 -57.4,-24.9 -57,-24.9 -50.5,-24.8 -50.1,-24.8 -49.7,-24.8 -42.095,-23.611 -56.6,-20.1 -56.6,-19.7 -56.6,-19.3
BUS12V: FL1.1 P4.A2 P4.A3 P4.B1 P4.B2 P4.B3 | length 43.3
  Top Layer w0.455: P4.B1@-36.35,-55.5 -36.228,-55.377 -36.228,-52.915 v6(-35.906,-52.594) ; P4.B2@-35.35,-55.5 -35.228,-55.377 -35.228,-53.04 v6(-34.781,-52.594) ; P4.B3@-34.35,-55.5 -34.228,-55.377 -34.228,-52.946 v6(-33.875,-52.594)
  Int6 (Sign) w2: -34.6,-51.9 -34.6,-51.839 -18.761,-36 FL1.1@-13.5,-36
  Bottom Layer w0.455: P4.A2@-35.35,-55.5 -35.228,-55.377 -35.228,-53.04 v6(-34.781,-52.594) ; P4.A3@-34.35,-55.5 -34.228,-55.377 -34.228,-52.946 v6(-33.875,-52.594)
CFG_CLK: P5.79 U16.AA3 | length 32.8
  Top Layer w0.127: U16.AA3@9.5,-8.5 v1(10,-9) ; P5.79@25.62,-28.605 v1(25.62,-27)
  Int3 (Sign) w0.127: v1(10,-9) ccw(c10,-9.5) 9.5,-9.5 9.5,-11 ccw(c10.5,-11) 10.5,-12 16.948,-12 cw(c16.948,-14.54) 18.744,-12.744 23.776,-17.776 ; 22.9,-16.9 24.876,-18.876 cw(c23.08,-20.672) 25.62,-20.672 v1(25.62,-27)
CFG_CS: P5.80 U16.AB1 | length 25.7
  Top Layer w0.127: U16.AB1@10.5,-10.5 10.646,-10.646 ccw(c11.5,-9.793) 11.5,-11 22.196,-11 cw(c22.196,-14.36) 25.556,-14.36 25.556,-22.722 ccw(c25.773,-22.722) P5.80@25.62,-22.875
CFG_SI: P5.77 U16.Y3 | length 31.8
  Top Layer w0.127: U16.Y3@8.5,-8.5 v1(9,-9) ; P5.77@24.82,-28.605 v1(24.82,-27)
  Int3 (Sign) w0.127: v1(9,-9) ccw(c9,-9.5) 8.5,-9.5 8.5,-11 ccw(c10.5,-11) 10.5,-13 16.948,-13 cw(c16.948,-15.54) 18.744,-13.744 24.076,-19.076 cw(c22.28,-20.872) 24.82,-20.872 v1(24.82,-27)
CFG_SO: P5.78 U16.AA1 | length 25.7
  Top Layer w0.127: U16.AA1@9.5,-10.5 10.339,-11.339 ccw(c11.5,-10.178) 11.5,-11.82 22.216,-11.82 cw(c22.216,-14.36) 24.756,-14.36 24.756,-22.722 ccw(c24.973,-22.722) P5.78@24.82,-22.875
CFGBVS: R130.1 U16.U8 | length 9.5
  Top Layer w0.127: U16.U8@5.5,-3.5 v1(6,-4)
  Bottom Layer w0.127: v1(6,-4) ccw(c7.207,-2.793) 7.207,-4.5 11.093,-4.5 cw(c11.093,-6.207) 12.3,-5 12.376,-5.076 ccw(c13.4,-4.051) 13.4,-5.5 R130.1@14.35,-5.5
CLOCK.ACLK_N: U16.AB22 U17.6 | length 22.7
  Top Layer w0.127: U16.AB22@10.5,10.5 ccw(c10.898,10.5) 10.898,10.102 ccw(c10.898,10.592) 11.245,10.245 13.297,12.297 cw(c15.235,10.359) 15.235,13.1 21.86,13.1 cw(c21.86,10.357) 24.603,10.357 24.603,9.002 cw(c22.5,9.002) 22.5,6.898 22.406,6.898 ccw(c22.406,6.517) 22.137,6.787 cw(c21.867,7.056) 21.867,6.675 U17.6@21.55,6.675
CLOCK.ACLK_P: U16.AB21 U17.5 | length 22
  Top Layer w0.127: U16.AB21@10.5,9.5 cw(c10.898,9.5) 10.898,9.898 ccw(c10.899,10.591) 11.389,10.101 13.44,12.153 cw(c15.236,10.357) 15.236,12.897 21.86,12.897 cw(c21.86,10.357) 24.4,10.357 24.4,9.002 cw(c22.5,9.002) 22.5,7.102 22.406,7.102 cw(c22.406,7.483) 22.137,7.213 ccw(c21.867,6.944) 21.867,7.325 U17.5@21.55,7.325
CLOCK.ACNV_N: U16.AA21 U17.8 | length 29.1
  Top Layer w0.127: U16.AA21@9.5,9.5 9.5,9.302 ccw(c9.7,9.302) 9.7,9.102 ccw(c9.7,9.302) 9.9,9.302 9.9,10.504 cw(c10.826,10.504) 10.171,11.159 12.31,13.297 cw(c14.248,11.359) 14.248,14.1 22.66,14.1 cw(c22.66,11.357) 25.403,11.357 25.403,8.342 cw(c22.66,8.342) 22.66,5.598 22.406,5.598 ccw(c22.406,5.217) 22.137,5.487 cw(c21.867,5.756) 21.867,5.375 U17.8@21.55,5.375
CLOCK.ACNV_P: U16.AA20 U17.7 | length 28.5
  Top Layer w0.127: U16.AA20@9.5,8.5 9.5,8.698 cw(c9.7,8.698) 9.7,8.898 ccw(c9.7,9.302) 10.103,9.302 10.103,10.503 cw(c10.827,10.503) 10.315,11.015 12.453,13.153 cw(c14.249,11.357) 14.249,13.897 22.66,13.897 cw(c22.66,11.357) 25.2,11.357 25.2,8.342 cw(c22.66,8.342) 22.66,5.802 22.406,5.802 cw(c22.406,6.183) 22.137,5.913 ccw(c21.867,5.644) 21.867,6.025 U17.7@21.55,6.025
CLOCK.AIN_N: U16.Y22 U17.10 | length 33.7
  Top Layer w0.127: U16.Y22@8.5,10.5 8.5,10.302 ccw(c8.7,10.302) 8.7,10.102 ccw(c8.7,10.302) 8.9,10.302 8.9,11.001 cw(c9.833,11.001) 9.173,11.661 11.81,14.297 cw(c13.748,12.359) 13.748,15.1 23.457,15.1 cw(c23.457,12.357) 26.2,12.357 26.2,7.042 cw(c23.457,7.042) 23.457,4.298 22.406,4.298 ccw(c22.406,3.917) 22.137,4.187 cw(c21.867,4.456) 21.867,4.075 U17.10@21.55,4.075
CLOCK.AIN_P: U16.Y21 U17.9 | length 33.1
  Top Layer w0.127: U16.Y21@8.5,9.5 8.5,9.698 cw(c8.7,9.698) 8.7,9.898 ccw(c8.7,10.302) 9.103,10.302 9.103,11 cw(c9.835,11) 9.317,11.517 11.953,14.153 cw(c13.749,12.357) 13.749,14.897 23.457,14.897 cw(c23.457,12.357) 25.997,12.357 25.997,7.042 cw(c23.457,7.042) 23.457,4.502 22.406,4.502 cw(c22.406,4.883) 22.137,4.613 ccw(c21.867,4.344) 21.867,4.725 U17.9@21.55,4.725
CLOCK.CNTROUT_N: U16.AB20 U17.4 | length 21
  Top Layer w0.127: U16.AB20@10.5,8.5 10.1,8.5 ccw(c10.1,8.3) 9.9,8.3 ccw(c10.098,8.3) 10.098,8.102 10.609,8.102 ccw(c10.609,9.398) 11.525,8.481 14.341,11.297 cw(c16.279,9.359) 16.279,12.1 21.784,12.1 cw(c21.784,10.081) 23.803,10.081 23.803,9.502 cw(c22.5,9.502) 22.5,8.198 22.406,8.198 ccw(c22.406,7.817) 22.137,8.087 cw(c21.867,8.356) 21.867,7.975 U17.4@21.55,7.975
CLOCK.CNTROUT_P: U16.AA19 U17.3 | length 20.1
  Top Layer w0.127: U16.AA19@9.5,7.5 cw(c9.898,7.5) 9.898,7.898 10.611,7.898 ccw(c10.611,9.392) 11.667,8.336 14.484,11.153 cw(c16.28,9.357) 16.28,11.897 21.703,11.897 cw(c21.703,10) 23.6,10 23.6,9.502 cw(c22.5,9.502) 22.5,8.402 22.406,8.402 cw(c22.406,8.783) 22.137,8.513 ccw(c21.867,8.244) 21.867,8.625 U17.3@21.55,8.625
CLOCK.OSCCLK_N: U16.Y19 U27.4 | length 48.5
  Top Layer w0.127: U16.Y19@8.5,7.5 v1(9,8) ; v2(49,-4.898) cw(c49,-5.078) 49.127,-4.951 ccw(c49.46,-4.618) 49.46,-5.088 ccw(c49.46,-4.748) 49.8,-4.748 U27.4@49.8,-3.8
  Int2 (Sign) w0.076: v1(9,8) 9,7.802 ccw(c9.2,7.802) 9.2,7.602 cw(c9.2,7.195) 9.606,7.195 ccw(c11.783,7.195) 10.244,5.656 18.556,-2.656 ccw(c20.352,-0.86) 20.352,-3.4 33.92,-3.4 cw(c33.92,-5.977) 35.742,-4.155 35.932,-4.344 ccw(c37.728,-2.548) 37.728,-5.088 48.54,-5.088 ccw(c48.54,-4.607) 48.88,-4.947 cw(c49,-5.067) v2(49,-4.898)
CLOCK.OSCCLK_P: U16.Y18 U27.5 | length 48
  Top Layer w0.127: U16.Y18@8.5,6.5 v1(9,7) ; v2(49,-5.482) ccw(c49,-5.302) 49.127,-5.429 cw(c49.46,-5.762) 49.46,-5.292 cw(c49.46,-5.632) 49.8,-5.632 U27.5@49.8,-6.1
  Int2 (Sign) w0.076: v1(9,7) 9,7.198 cw(c9.2,7.198) 9.2,7.398 cw(c9.2,7.195) 9.403,7.195 9.403,7.111 ccw(c11.58,7.111) 10.041,5.572 10.057,5.555 18.413,-2.8 ccw(c20.351,-0.861) 18.415,-2.803 ccw(c20.351,-0.861) 20.351,-3.603 33.918,-3.603 cw(c33.918,-5.982) 35.6,-4.3 35.788,-4.488 ccw(c37.728,-2.549) 37.724,-5.292 ccw(c37.728,-2.549) 37.728,-5.292 48.54,-5.292 cw(c48.54,-5.773) 48.88,-5.433 ccw(c49,-5.313) v2(49,-5.482)
CLOCK.SYNC_N: U16.AB18 U17.2 | length 17.9
  Top Layer w0.127: U16.AB18@10.5,6.5 10.302,6.5 ccw(c10.302,6.3) 10.102,6.3 ccw(c10.302,6.3) 10.302,6.1 10.534,6.1 ccw(c10.534,7.466) 11.5,6.5 15.3,10.3 cw(c17.238,8.363) 17.238,11.103 21.9,11.103 cw(c21.9,10) 23.003,10 cw(c22.502,10) 22.502,9.498 22.406,9.498 ccw(c22.406,9.117) 22.137,9.387 cw(c21.867,9.656) 21.867,9.275 U17.2@21.55,9.275
CLOCK.SYNC_P: U16.AA18 U17.1 | length 17.5
  Top Layer w0.127: U16.AA18@9.5,6.5 9.698,6.5 cw(c9.698,6.3) 9.898,6.3 ccw(c10.302,6.3) 10.302,5.897 10.537,5.897 ccw(c10.537,7.459) 11.642,6.354 15.443,10.156 cw(c17.239,8.36) 17.239,10.9 21.9,10.9 cw(c21.9,10) 22.8,10 cw(c22.502,10) 22.502,9.702 22.406,9.702 cw(c22.406,10.083) 22.137,9.813 ccw(c21.867,9.544) 21.867,9.925 U17.1@21.55,9.925
CONFIG.SW1: S1.16 U16.T20 | length 68.6
  Top Layer w0.127: v1(-43.71,39) S1.16@-43.71,40.85 ; U16.T20@4.5,8.5 v1(5,9)
  Int3 (Sign) w0.127: v1(-43.71,39) -42.954,38.244 ccw(c-41.158,40.04) -41.158,37.5 -37.9,37.5 ; -38,37.5 -17.752,37.5 cw(c-17.752,27.96) -11.006,34.706 1.706,21.994 cw(c-5.04,15.248) 4.5,15.248 4.5,9.5 ccw(c5,9.5) v1(5,9)
CONFIG.SW2: S1.15 U16.P20 | length 70.1
  Top Layer w0.127: v1(-46.25,39) S1.15@-46.25,40.85 ; U16.P20@2.5,8.5 v1(3,9)
  Int3 (Sign) w0.127: v1(-46.25,39) -44.494,37.244 ccw(c-42.698,39.04) -42.698,36.5 -37.8,36.5 ; -38,36.5 -17.752,36.5 cw(c-17.752,27.96) -11.713,33.999 0.999,21.287 cw(c-5.04,15.248) 3.5,15.248 3.5,9.5 cw(c3,9.5) v1(3,9)
CONFIG.SW3: S1.14 U16.N19 | length 72.9
  Top Layer w0.127: v1@-48.8,39 ccw(c-48.824,39.024) v1@-48.79,39.024 ; v1(-48.79,39) S1.14@-48.79,40.85 ; U16.N19@1.5,7.5 v1(2,8)
  Int3 (Sign) w0.127: v1(-48.79,39) -46.034,36.244 ccw(c-44.238,38.04) -44.238,35.5 -37.4,35.5 ; -38,35.5 -17.752,35.5 cw(c-17.752,27.96) -12.421,33.292 0.292,20.579 cw(c-5.04,15.248) 2.5,15.248 2.5,8.5 cw(c2,8.5) v1(2,8)
CONFIG.SW4: S1.13 U16.N18 | length 75.7
  Top Layer w0.127: v1@-51.4,39 ccw(c-51.569,39.169) v1@-51.33,39.169 ; v1(-51.33,39) S1.13@-51.33,40.85 ; U16.N18@1.5,6.5 v1(2,7)
  Int3 (Sign) w0.127: v1(-51.33,39) -47.574,35.244 ccw(c-45.778,37.04) -45.778,34.5 -37.2,34.5 ; -38,34.5 -17.752,34.5 cw(c-17.752,27.96) -13.128,32.585 -0.415,19.872 cw(c-5.04,15.248) 1.5,15.248 1.5,7.5 ccw(c2,7.5) v1(2,7)
CONFIG.SW5: S1.12 U16.N15 | length 79.9
  Top Layer w0.127: v1@-53.9,39 ccw(c-53.972,39.072) v1@-53.87,39.072 ; v1(-53.87,39) S1.12@-53.87,40.85 ; U16.N15@1.5,3.5 v1(2,4)
  Int3 (Sign) w0.127: v1(-53.87,39) -49.114,34.244 ccw(c-47.318,36.04) -47.318,33.5 -17.752,33.5 cw(c-17.752,27.96) -13.835,31.877 -1.123,19.165 cw(c-5.04,15.248) 0.5,15.248 0.5,5 ccw(c1,5) 1,4.5 1.5,4.5 cw(c1.5,4) v1(2,4)
CONFIG.SW6: S1.11 U16.N14 | length 84.4
  Top Layer w0.127: v1(-56.41,39) S1.11@-56.41,40.85 ; U16.N14@1.5,2.5 v1(2,3)
  Int3 (Sign) w0.127: v1(-56.41,39) -50.654,33.244 ccw(c-48.858,35.04) -48.858,32.5 -36.6,32.5 ; -38,32.5 -17.752,32.5 cw(c-17.752,27.96) -14.542,31.17 -1.83,18.458 cw(c-5.04,15.248) -0.5,15.248 -0.5,4.5 ccw(c0.5,4.5) 0.5,3.5 1.5,3.5 cw(c1.5,3) v1(2,3)
CONFIG.SW7: S1.10 U16.K2 | length 105.6
  Top Layer w0.127: v1@-59,39 ccw(c-59.121,39.121) v1@-58.95,39.121 ; v1(-58.95,39) S1.10@-58.95,40.85 ; v1(-2,-10) U16.K2@-1.5,-9.5
  Int3 (Sign) w0.127: v1(-58.95,39) -52.194,32.244 ccw(c-50.398,34.04) -50.398,31.5 -37.6,31.5 ; -38,31.5 -17.752,31.5 cw(c-17.752,27.96) -15.249,30.463 -2.537,17.751 cw(c-5.04,15.248) -1.5,15.248 -1.5,3 ccw(c-1,3) -1,2.5 3,2.5 cw(c3,2) 3.5,2 3.5,-9 cw(c3,-9) 3,-9.5 -1,-9.5 ccw(c-1,-10.707) -1.513,-9.615 ccw(c-1,-10.707) -1.853,-9.853 v1(-2,-10)
CONFIG.SW8: S1.9 U16.J2 | length 106.4
  Top Layer w0.127: v1(-61.49,39) S1.9@-61.49,40.85 ; v1(-3,-10) U16.J2@-2.5,-9.5
  Int3 (Sign) w0.127: v1(-61.49,39) -53.734,31.244 ccw(c-51.938,33.04) -51.938,30.5 -17.749,30.5 ; -17.7,30.5 -17.749,30.5 ; v1(-3,-10) ccw(c-3,-9.5) -2.5,-9.5 -2.5,-9 cw(c-2,-9) -2,-8.5 2,-8.5 ccw(c2,-8) 2.5,-8 2.5,1 ccw(c2,1) 2,1.5 -2,1.5 cw(c-2,2) -2.5,2 -2.5,15.248 ccw(c-5.04,15.248) -3.244,17.044 -15.956,29.756 ccw(c-17.752,27.96) -17.749,30.5
CONFIG.SW9: P5.6 U16.N13 | length 39.1
  Top Layer w0.127: v1(-7.98,-24.5) P5.6@-7.98,-22.875 ; U16.N13@1.5,1.5 v1(2,2)
  Int7 (Sign) w0.127: v1(-7.98,-24.5) -8.756,-23.724 cw(c-6.96,-21.928) -9.5,-21.928 -9.5,-6 cw(c-8,-6) -8,-4.5 -1,-4.5 ccw(c-1,-3) 0.5,-3 0.5,1 cw(c1,1) 1,1.5 1.5,1.5 ccw(c1.5,2) v1(2,2)
CONFIG.SW10: P5.8 U16.L6 | length 27.9
  Top Layer w0.127: v1(-7.18,-24.5) P5.8@-7.18,-22.875 ; v1(-1,-6) U16.L6@-0.5,-5.5
  Int7 (Sign) w0.127: v1(-7.18,-24.5) -7.756,-23.924 cw(c-5.96,-22.128) -8.5,-22.128 -8.5,-8 cw(c-7,-8) -7,-6.5 -1.5,-6.5 ccw(c-1.5,-6) v1(-1,-6)
D0IN: U11.1 U14.11 | length 25.2
  Top Layer w0.127: U11.1@-39.2,-38.525 -38.725,-38.525 -38.563,-38.363 -38.563,-37.063 -38,-36.5 -38,-21 -34.025,-17.025 U14.11@-32.775,-17.025
D1IN: U12.1 U14.10 | length 16.4
  Top Layer w0.127: U12.1@-38.7,-29.1 -38.6,-29 -38.6,-20.1 -34.875,-16.375 U14.10@-32.775,-16.375
DAC_REF.DOUT0_N: U14.6 U16.B2 | length 23.3
  Top Layer w0.127: U14.6@-27.225,-17.025 -26.55,-17.025 -26.463,-17.111 -26.463,-17.174 -26.389,-17.248 -26.265,-17.248 -26.074,-17.058 v2(-26,-17.058) ; v1(-10,-10) U16.B2@-9.5,-9.5
  Int2 (Sign) w0.076: v2(-26,-17.058) -25.93,-17.058 -25.739,-17.248 -15.186,-17.248 ccw(c-15.186,-14.302) -13.103,-16.385 -10.346,-13.628 ccw(c-12.142,-11.832) -9.602,-11.832 -9.602,-10.398 ccw(c-10,-10.398) v1(-10,-10)
  Bottom Layer w0.127: v2@-26,-17.085 v2(-26,-17.058)
DAC_REF.DOUT0_P: U14.5 U16.C2 | length 23.8
  Top Layer w0.127: U14.5@-27.225,-17.675 -26.55,-17.675 -26.463,-17.589 -26.463,-17.526 -26.389,-17.452 -26.265,-17.452 -26.074,-17.642 v2(-26,-17.642) ; v1(-9,-10) U16.C2@-8.5,-9.5
  Int2 (Sign) w0.076: v2(-26,-17.642) -25.93,-17.642 -25.739,-17.452 -15.186,-17.452 ccw(c-15.186,-14.302) -12.959,-16.529 -10.201,-13.771 ccw(c-12.14,-11.833) -9.398,-11.833 -9.398,-10.398 cw(c-9,-10.398) v1(-9,-10)
  Bottom Layer w0.127: v2(-26,-17.642) v2@-26,-17.452
DAC_REF.DOUT1_N: U14.8 U16.A1 | length 20.3
  Top Layer w0.127: U14.8@-27.225,-15.725 -26.55,-15.725 -26.463,-15.811 -26.463,-15.874 -26.389,-15.948 -26.265,-15.948 -26.074,-15.758 v2(-26,-15.758) ; v1(-11,-11) U16.A1@-10.5,-10.5
  Int2 (Sign) w0.076: v2(-26,-15.758) -25.93,-15.758 -25.739,-15.948 -15.557,-15.948 ccw(c-15.557,-13.408) -13.761,-15.204 -11.059,-12.503 ccw(c-12.164,-11.398) -10.602,-11.398 ccw(c-11,-11.398) v1(-11,-11)
DAC_REF.DOUT1_P: U14.7 U16.B1 | length 20.8
  Top Layer w0.127: U14.7@-27.225,-16.375 -26.55,-16.375 -26.463,-16.289 -26.463,-16.226 -26.389,-16.152 -26.265,-16.152 -26.074,-16.342 v2(-26,-16.342) ; v1(-10,-11) U16.B1@-9.5,-10.5 U16.B1@-9.5,-10.4
  Int2 (Sign) w0.076: v2(-26,-16.342) -25.93,-16.342 -25.739,-16.152 -15.557,-16.152 ccw(c-15.557,-13.408) -13.617,-15.348 -10.913,-12.645 ccw(c-12.157,-11.401) -10.398,-11.401 -10.398,-11.398 cw(c-10,-11.398) v1(-10,-11)
DAC_REF.DSCLK_N: U14.2 U16.D1 | length 26.3
  Top Layer w0.127: U14.2@-27.225,-19.625 -26.55,-19.625 -26.463,-19.711 -26.463,-19.774 -26.389,-19.848 -26.265,-19.848 -26.074,-19.658 v2(-26,-19.658) ; v1(-8,-11) U16.D1@-7.5,-10.5
  Int2 (Sign) w0.076: v2(-26,-19.658) -25.93,-19.658 -25.739,-19.848 -14.446,-19.848 ccw(c-14.446,-16.089) -11.788,-18.747 -8.346,-15.305 ccw(c-10.142,-13.509) -7.602,-13.509 -7.602,-11.398 ccw(c-8,-11.398) v1(-8,-11)
DAC_REF.DSCLK_P: U14.1 U16.E1 | length 26.6
  Top Layer w0.127: U14.1@-27.225,-20.275 -26.55,-20.275 -26.463,-20.189 -26.463,-20.126 -26.389,-20.052 -26.265,-20.052 -26.074,-20.242 v2(-26,-20.242) ; v1(-7,-11) U16.E1@-6.5,-10.5
  Int2 (Sign) w0.076: v2(-26,-20.242) -25.93,-20.242 -25.739,-20.052 -14.446,-20.052 ccw(c-14.446,-16.089) -11.644,-18.891 -8.201,-15.448 ccw(c-10.139,-13.51) -7.398,-13.51 -7.398,-11.398 cw(c-7,-11.398) v1(-7,-11)
DAC_REF.DSYNC_N: U14.4 U16.D2 | length 26.1
  Top Layer w0.127: U14.4@-27.225,-18.325 -26.55,-18.325 -26.463,-18.411 -26.463,-18.474 -26.389,-18.548 -26.265,-18.548 -26.074,-18.358 v2(-26,-18.358) ; v1(-8,-10) U16.D2@-7.5,-9.5
  Int2 (Sign) w0.076: v2(-26,-18.358) -25.93,-18.358 -25.739,-18.548 -14.816,-18.548 ccw(c-14.816,-15.196) -12.445,-17.566 -9.347,-14.468 ccw(c-11.143,-12.672) -8.603,-12.672 -8.603,-11.003 cw(c-8,-11.003) -8,-10.4 -7.702,-10.4 ccw(c-7.702,-10.3) -7.602,-10.3 ccw(c-7.902,-10.3) -7.902,-10 v1(-8,-10)
DAC_REF.DSYNC_P: U14.3 U16.E2 | length 26.3
  Top Layer w0.127: U14.3@-27.225,-18.975 -26.55,-18.975 -26.463,-18.889 -26.463,-18.826 -26.389,-18.752 -26.265,-18.752 -26.074,-18.942 v2(-26,-18.942) ; v1(-7,-10) -6.6,-9.6 U16.E2@-6.5,-9.6
  Int2 (Sign) w0.076: v2(-26,-18.942) -25.93,-18.942 -25.739,-18.752 -14.816,-18.752 ccw(c-14.816,-15.196) -12.302,-17.71 -9.203,-14.611 ccw(c-11.142,-12.673) -8.4,-12.673 -8.4,-11.003 cw(c-8,-11.003) -8,-10.603 -7.702,-10.603 ccw(c-7.702,-10.3) -7.398,-10.3 cw(c-7.098,-10.3) -7.098,-10 v1(-7,-10)
DAC_REF.INVSYNC_N: U16.W5 U35.4 | length 41.9
  Top Layer w0.127: U16.W5@7.5,-6.5 v1(8,-7)
  Int3 (Sign) w0.076: v1(8,-7) 8,-6.802 ccw(c7.8,-6.802) 7.8,-6.602 ccw(c7.8,-6.802) 7.6,-6.802 7.6,-8 ccw(c8,-8) 8,-8.4 10,-8.4 cw(c10,-9.003) 10.603,-9.003 10.603,-10.403 ccw(c11.1,-10.403) 11.1,-10.9 17.412,-10.9 cw(c17.412,-13.64) 19.349,-11.702 25.802,-18.155 cw(c23.866,-20.09) 26.603,-20.09 26.603,-27.888 cw(c24.892,-27.888) 26.102,-29.098 25.846,-29.354 ccw(c27.642,-31.151) 25.102,-31.151 25.102,-31.24 ccw(c25.583,-31.24) 25.243,-31.58 cw(c25.123,-31.7) v2(25.292,-31.7)
  Bottom Layer w0.127: v2(25.292,-31.7) ccw(c26.142,-31.7) 26.142,-32.55 U35.4@26.35,-32.55
DAC_REF.INVSYNC_P: U16.W6 U35.3 | length 42.2
  Top Layer w0.127: U16.W6@7.5,-5.5 v1(8,-6)
  Int3 (Sign) w0.076: v1(8,-6) 8,-6.198 cw(c7.8,-6.198) 7.8,-6.398 ccw(c7.8,-6.802) 7.397,-6.802 7.397,-8 ccw(c8,-8) 8,-8.603 10,-8.603 cw(c10,-9.003) 10.4,-9.003 10.4,-10.403 ccw(c11.1,-10.403) 11.1,-11.103 17.41,-11.103 cw(c17.41,-13.643) 19.206,-11.847 25.656,-18.297 cw(c23.86,-20.093) 26.4,-20.093 26.4,-27.885 cw(c24.885,-27.885) 25.956,-28.956 25.701,-29.212 ccw(c27.639,-31.149) 24.898,-31.149 24.898,-31.24 cw(c24.417,-31.24) 24.757,-31.58 ccw(c24.877,-31.7) v2(24.708,-31.7)
  Bottom Layer w0.127: U35.3@23.65,-32.55 23.858,-32.55 ccw(c23.858,-31.7) v2(24.708,-31.7)
DAC_REF.REFCLK_N: U16.W20 U29.6 | length 71.5
  Top Layer w0.127: U16.W20@7.5,8.5 v1(8,9) ; v2(67.5,28.792) cw(c67.5,28.612) 67.627,28.739 67.677,28.689 ccw(c67.889,28.901) 67.889,28.602 ccw(c67.889,28.856) 68.068,28.676 68.068,28.678 68.142,28.752 cw(c68.319,28.575) 68.319,28.825 U29.6@68.805,28.825
  Int2 (Sign) w0.076: v1(8,9) 8,8.8 ccw(c8.198,8.8) 8.198,8.602 ccw(c8.198,8.803) 8.4,8.803 8.4,11.002 cw(c9.333,11.002) 8.673,11.662 15.009,17.998 cw(c16.945,16.063) 16.945,18.8 55.562,18.8 ccw(c55.562,21.34) 57.358,19.544 65.862,28.048 cw(c67.199,26.71) 65.864,28.05 cw(c67.199,26.71) 67.199,28.602 ccw(c67.2,28.697) 67.267,28.63 67.38,28.743 cw(c67.5,28.623) v2(67.5,28.792)
DAC_REF.REFCLK_P: U16.W19 U29.7 | length 71.5
  Top Layer w0.127: U16.W19@7.5,7.5 v1(8,8) ; v2(67.5,28.208) ccw(c67.5,28.388) 67.627,28.261 67.677,28.311 cw(c67.889,28.099) 67.889,28.398 cw(c67.889,28.144) 68.068,28.324 68.068,28.321 68.142,28.248 ccw(c68.319,28.425) 68.319,28.175 U29.7@68.805,28.175
  Int2 (Sign) w0.076: v1(8,8) 8,8.2 cw(c8.198,8.2) 8.198,8.398 ccw(c8.198,8.803) 8.603,8.803 8.603,11 cw(c9.339,11) 8.819,11.52 15.151,17.853 cw(c16.947,16.057) 16.947,18.597 55.563,18.597 ccw(c55.563,21.337) 57.501,19.4 66.005,27.903 cw(c67.2,26.708) 67.2,28.398 cw(c67.2,28.303) 67.267,28.37 67.38,28.257 ccw(c67.5,28.377) v2(67.5,28.208)
DONE: Q1.1 R25.1 U16.G11 | length 30.1
  Top Layer w0.127: R25.1@-29.4,-8.1 R25.1@-29.3,-8.1 ; R25.1@-29.4,-8 R25.1@-29.35,-8 -28.052,-8 ccw(c-28.052,-5.46) -26.256,-7.256 -19.744,-0.744 cw(c-17.948,-2.54) -17.948,0 -15,0 -5,0 cw(c-5,-0.5) U16.G11@-4.5,-0.5 ; Q1.1@-29.3,-9.625 Q1.1@-29.05,-9.875
  Top Layer w0.203: Q1.1@-29.3,-9.625 v3@-29.3,-9.1 ; v3@-29.3,-8.9 R25.1@-29.3,-8.1
  other v3: -29.3,-9
DUOTONE_N: P1.36 R1.2 | length 20.6
  Top Layer w0.127: P1.36@-74.795,-27.4 cw(c-74.666,-27.529) -74.666,-27.346 -73.234,-27.346 cw(c-73.234,-27.473) -73.144,-27.384 cw(c-73.234,-27.473) -73.107,-27.473 -73.107,-29.083 cw(c-73.88,-29.083) -73.333,-29.629 ccw(c-72.787,-30.176) -73.56,-30.176 -73.56,-32.792 ccw(c-70.818,-32.792) -72.756,-34.731 -68.689,-38.799 ccw(c-66.75,-36.86) -66.75,-39.602 -64.631,-39.602 cw(c-64.631,-39.729) -64.541,-39.639 cw(c-64.631,-39.729) -64.504,-39.729 -64.504,-39.811 ccw(c-64.179,-39.811) -64.409,-40.041 R1.2@-63.95,-40.5
DUOTONE_P: P1.17 R2.2 | length 20.4
  Top Layer w0.127: P1.17@-71.955,-26.015 -73,-27.06 ccw(c-72.91,-27.15) -73.037,-27.15 ccw(c-72.91,-27.15) -73,-27.24 -72.999,-27.241 cw(c-73.23,-27.472) -72.904,-27.472 -72.904,-29.167 cw(c-73.676,-29.167) -73.13,-29.713 ccw(c-72.583,-30.26) -73.356,-30.26 -73.356,-32.792 ccw(c-70.816,-32.792) -72.612,-34.588 -68.546,-38.654 ccw(c-66.749,-36.858) -66.749,-39.398 -64.631,-39.398 ccw(c-64.631,-39.271) -64.541,-39.361 ccw(c-64.631,-39.271) -64.504,-39.271 -64.504,-39.189 cw(c-64.179,-39.189) R2.2@-64.409,-38.959 ; R2.2@-64.409,-38.959 R2.2@-63.95,-38.5
EXT12V: C77.1 C78.1 FL4.1 J2.1 J2.2 J2.3 TP25.1 | length 4.1
  Bottom Layer w1: FL4.1@74.5,-27 74.5,-27.189 75.95,-28.639 75.95,-30.425 C77.1@76.025,-30.5
EXT_SYNC.EXTSYNC_N: U16.L13 U39.4 | length 46.4
  Top Layer w0.127: U16.L13@-0.5,1.5 v1(0,2)
  Bottom Layer w0.127: U39.4@-26.05,24.15 -26.05,24.709 cw(c-25.361,24.709) -25.361,25.398 -24.143,25.398 cw(c-24.143,22.858) -21.603,22.858 -21.603,14.603 ccw(c-18.862,14.603) -20.8,12.665 -17.335,9.2 ccw(c-15.396,11.139) -15.396,8.397 -10,8.397 cw(c-10,8) -9.603,8 -9.603,6 ccw(c-9.003,6) -9.003,5.4 -1,5.4 cw(c-1,4.002) 0.398,4.002 0.398,2.398 cw(c0,2.398) v1(0,2)
EXT_SYNC.EXTSYNC_P: U16.M13 U39.3 | length 46.7
  Top Layer w0.127: U16.M13@0.5,1.5 v1(1,2)
  Bottom Layer w0.127: U39.3@-26.05,26.85 -26.05,26.291 ccw(c-25.361,26.291) -25.361,25.602 -24.143,25.602 cw(c-24.143,22.858) -21.4,22.858 -21.4,14.604 ccw(c-18.86,14.604) -20.656,12.808 -17.192,9.344 ccw(c-15.396,11.14) -15.396,8.6 -10,8.6 cw(c-10,8) -9.4,8 -9.4,6 ccw(c-9.003,6) -9.003,5.603 -1,5.603 cw(c-1,4.002) 0.602,4.002 0.602,2.398 ccw(c1,2.398) v1(1,2)
FAULT: J1.2 R111.1 | length 3.2
  Top Layer w0.203: J1.2@57.7,40.47 v1(59.5,40.47)
  Bottom Layer w0.203: R111.1@58.15,40.47 v1(59.5,40.47)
